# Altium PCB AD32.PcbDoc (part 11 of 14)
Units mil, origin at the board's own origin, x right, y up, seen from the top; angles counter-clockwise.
Board outline 7007.87 x 4368.85 mil, 12 copper layers (Top Layer, Int1 (GND), Int2 (AVDD), Int3 (DVDD), Int4 (GND), Int5 (ST), Int6 (SB), Int8 (AGND), Int7 (AVCC), Int9 (VCCA), Int10 (GND), Bottom Layer), stack 60.136 mil thick; 1350 components, 880 nets, 4712 pads, 2835 vias.
Unrouted connection lines stored in the file: 19.
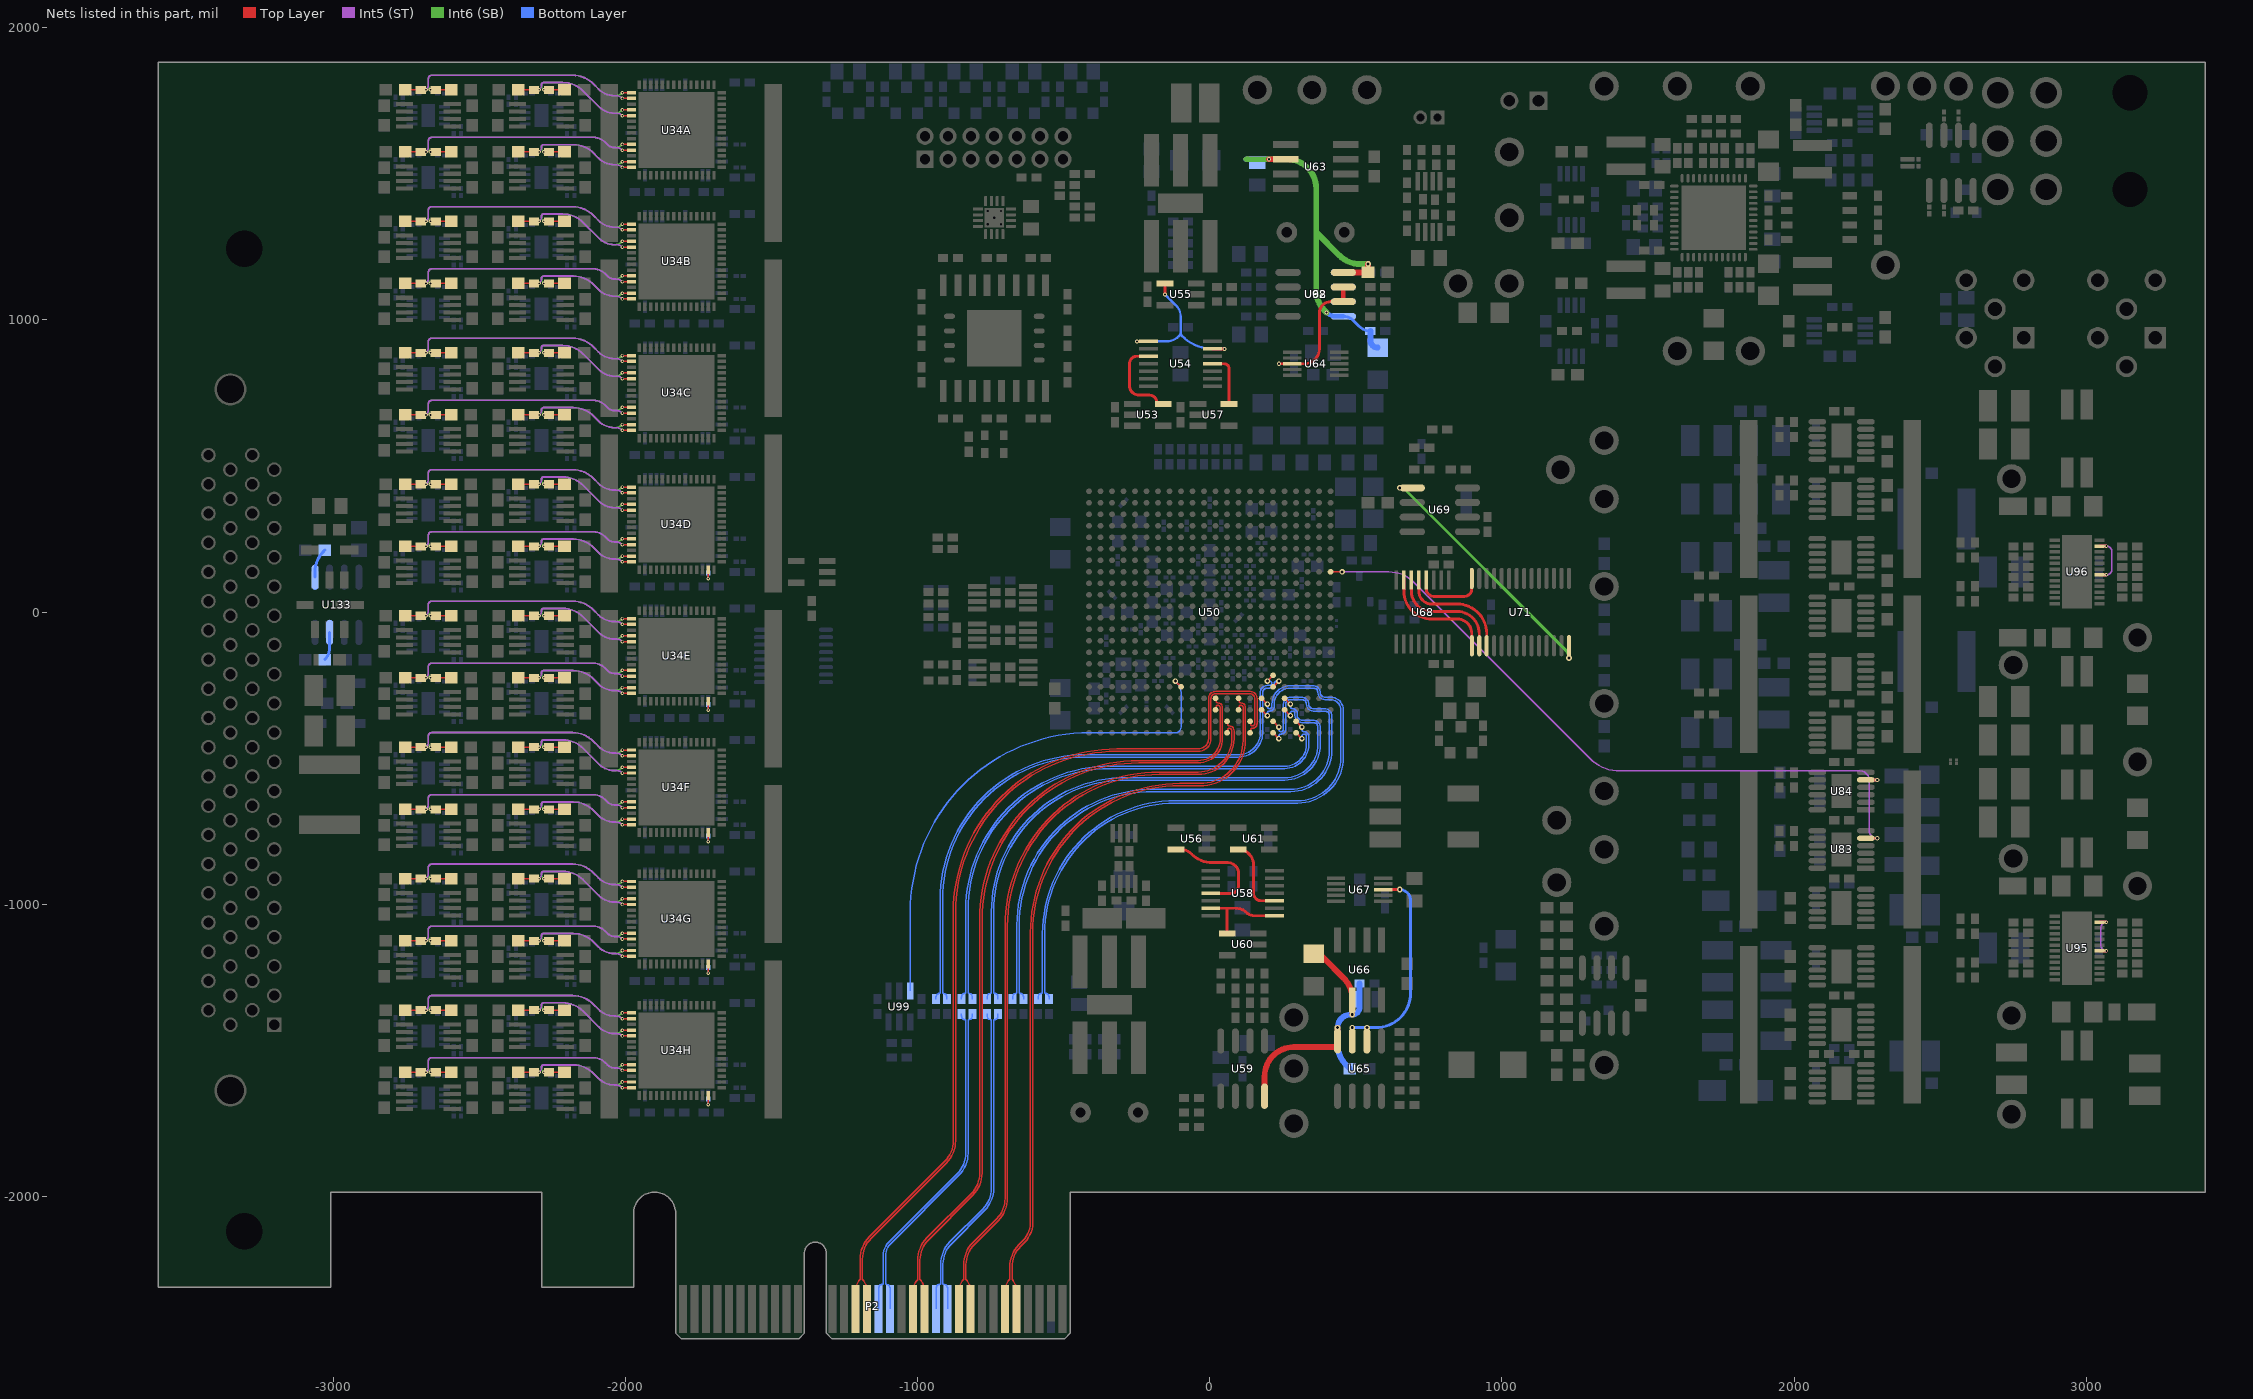
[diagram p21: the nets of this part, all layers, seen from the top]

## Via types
v1: diameter 12, hole 6, Top Layer to Bottom Layer, tented both sides, 1497 vias
v2: diameter 20, hole 10, Top Layer to Bottom Layer, tented both sides, 364 vias
v3: diameter 19, hole 10, Top Layer to Bottom Layer, tented both sides, 347 vias
v4: diameter 14, hole 7, Top Layer to Bottom Layer, tented both sides, 228 vias
v5: diameter 19.68, hole 7.87, Top Layer to Bottom Layer, 225 vias
v6: diameter 19.02, hole 10, Top Layer to Bottom Layer, tented both sides, 85 vias
v7: diameter 20, hole 10, Top Layer to Bottom Layer, 32 vias
v8: diameter 40, hole 20, Top Layer to Bottom Layer, tented both sides, 14 vias
v9: diameter 30, hole 15, Top Layer to Bottom Layer, tented both sides, 12 vias
v10: diameter 25, hole 13, Top Layer to Bottom Layer, 8 vias
v11: diameter 40, hole 20, Top Layer to Bottom Layer, 6 vias
v12: diameter 50, hole 20, Top Layer to Bottom Layer, 6 vias
v13: diameter 66, hole 47, Top Layer to Bottom Layer, tented both sides, 3 vias
v14: diameter 63, hole 45, Top Layer to Bottom Layer, 2 vias
v15: diameter 50, hole 25, Top Layer to Bottom Layer, 2 vias
v16: diameter 12, hole 6, Top Layer to Bottom Layer, 2 vias
v17: diameter 60, hole 40, Top Layer to Bottom Layer, tented both sides, 1 vias
v18: diameter 60, hole 40, Top Layer to Bottom Layer, 1 vias

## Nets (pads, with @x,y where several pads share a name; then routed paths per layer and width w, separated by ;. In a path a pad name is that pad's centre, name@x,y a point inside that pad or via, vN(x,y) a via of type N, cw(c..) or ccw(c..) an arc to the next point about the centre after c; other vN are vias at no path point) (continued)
NetR457D_1: R457D.1 U34D.55 | length 49.7
  Top Layer w5: v1(-1716.73,114.57) U34D.55@-1716.73,145.38
  Bottom Layer w5: v1(-1716.73,114.57) R457D.1@-1716.73,133.44
NetR457E_1: R457E.1 U34E.55 | length 49.7
  Top Layer w5: v1(-1716.73,-335.43) U34E.55@-1716.73,-304.62
  Bottom Layer w5: v1(-1716.73,-335.43) R457E.1@-1716.73,-316.56
NetR457F_1: R457F.1 U34F.55 | length 49.7
  Top Layer w5: v1(-1716.73,-785.43) U34F.55@-1716.73,-754.62
  Bottom Layer w5: v1(-1716.73,-785.43) R457F.1@-1716.73,-766.56
NetR457G_1: R457G.1 U34G.55 | length 49.7
  Top Layer w5: v1(-1716.73,-1235.43) U34G.55@-1716.73,-1204.62
  Bottom Layer w5: v1(-1716.73,-1235.43) R457G.1@-1716.73,-1216.56
NetR457H_1: R457H.1 U34H.55 | length 49.7
  Top Layer w5: v1(-1716.73,-1685.43) U34H.55@-1716.73,-1654.62
  Bottom Layer w5: v1(-1716.73,-1685.43) R457H.1@-1716.73,-1666.56
NetR665_1: R665.1 U133.3 | length 97.4
  Bottom Layer w10: R665.1@-3029.04,-162.5 ccw(c-3068.96,-122.58) -3012.5,-122.58 U133.3@-3012.5,-69.49
NetR666_1: R666.1 U133.5 | length 102.6
  Bottom Layer w10: U133.5@-3062.5,119.49 -3062.5,137.61 cw(c-2962.5,137.61) -3033.21,208.32 R666.1@-3029.04,212.5
NetU53_5: U53.5 U54.3 | length 332.7
  Top Layer w10: U54.3@-209.25,875.59 -250,875.59 ccw(c-250,850.59) -275,850.59 -275,775 ccw(c-242.5,775) -242.5,742.5 -205.89,742.5 cw(c-205.89,718.31) U53.5@-181.69,718.31 ; U53.5@-181.69,718.31 ccw(c-175.79,718.31) -175.79,712.4 U53.5@-159.35,712.4 ccw(c-165.26,712.4) -165.26,718.31 U53.5@-181.69,718.31
NetU54_1: U54.1 U54.13 U55.4 | length 602.1
  Top Layer w10: v4(-249.61,926.77) U54.1@-209.25,926.77 ; v4(-153.15,1087.5) U55.4@-153.15,1124.9 ; U54.13@9.25,901.18 v4(50,901.18)
  Bottom Layer w8: v4(-249.61,926.77) -148.58,926.77 ccw(c-148.58,987.97) -105.3,944.7 ccw(c-118.11,957.5) -100,957.5 ; v4(-153.15,1087.5) -115.45,1049.8 cw(c-152.75,1012.5) -100,1012.5 -100,957.5 ; v4(50,901.18) 10.36,901.18 cw(c10.36,1049.75) -94.7,944.7 cw(c-81.89,957.5) -100,957.5
NetU54_11: U54.11 U57.5 | length 187.3
  Top Layer w10: U54.11@9.25,850 50,850 cw(c50,834.35) 65.65,834.35 U57.5@65.65,712.4
NetU56_5: U56.5 U58.11 | length 399.6
  Top Layer w10: U56.5@-115.65,-812.4 -99.71,-812.4 cw(c-99.71,-865.03) -62.5,-827.81 -62.1,-828.21 ccw(c8.61,-757.5) 8.61,-857.5 61.61,-857.5 cw(c61.61,-894.31) 98.43,-894.31 98.43,-937.01 cw(c72.93,-937.01) 72.93,-962.5 U58.11@3.25,-962.5
NetU58_1: U58.1 U58.13 U60.4 | length 312.4
  Top Layer w10: U58.13@3.25,-1013.68 61.56,-1013.68 ; U60.4@59.35,-1100.1 59.35,-1019 cw(c66.88,-1019) 61.56,-1013.68 ; U58.1@221.75,-1039.27 152.38,-1039.27 cw(c152.38,-1000.97) 125.3,-1028.05 ccw(c90.6,-1062.75) 90.6,-1013.68 61.56,-1013.68
NetU58_3: U58.3 U61.5 | length 266.8
  Top Layer w10: U61.5@96.85,-812.4 cw(c96.85,-865.55) 150,-865.55 150,-962.5 ccw(c175.59,-962.5) 175.59,-988.09 U58.3@221.75,-988.09
NetU62_6: U62.6 U62.7 U64.3 | length 444.1
  Top Layer w10: v4(237.5,850) U64.3@281.79,850 325,850 ccw(c325,900) 375,900 375,1024.31 cw(c413.19,1024.31) 413.19,1062.5 U62.6@456.99,1062.5
  Top Layer w15: U62.6@456.99,1062.5 U62.7@456.99,1112.5
NetU65_6: U65.6 U65.7 U67.3 | length 790.4
  Top Layer w10: U65.7@487.5,-1468.01 v2(487.5,-1422.5) ; U65.6@537.5,-1468.01 v2(537.5,-1422.5) ; U67.3@593.21,-950 v2(650,-950)
  Bottom Layer w10: v2(487.5,-1422.5) v2(537.5,-1422.5) 567.87,-1422.5 ccw(c567.87,-1302.87) 687.5,-1302.87 687.5,-987.5 ccw(c650,-987.5) v2(650,-950)
NetU68_4: U68.4 U71.14 | length 250.3
  Top Layer w10: U68.4@741.14,109.25 741.14,79.16 ccw(c766.26,79.16) 766.26,54.04 871.63,54.04 ccw(c871.63,79.06) 896.65,79.06 U71.14@896.65,115.16
NetU68_5: U68.5 U71.17 | length 394.2
  Top Layer w10: U68.5@715.55,109.25 715.55,71.77 ccw(c759.76,71.77) 759.76,27.56 846.54,27.56 cw(c846.54,-73.74) 947.83,-73.74 U71.17@947.83,-115.16
NetU68_6: U68.6 U71.16 | length 394.2
  Top Layer w10: U68.6@689.96,109.25 689.96,71.77 ccw(c759.76,71.77) 759.76,1.97 846.54,1.97 cw(c846.54,-73.74) 922.24,-73.74 U71.16@922.24,-115.16
NetU68_7: U68.7 U71.15 | length 394.2
  Top Layer w10: U68.7@664.37,109.25 664.37,71.77 ccw(c759.76,71.77) 759.76,-23.62 846.54,-23.62 cw(c846.54,-73.74) 896.65,-73.74 U71.15@896.65,-115.16
NetU69_5: U69.5 U71.28 | length 869.2
  Top Layer w10: v2(1229.33,-157.48) U71.28@1229.33,-115.16
  Int6 (SB) w10: v3(650,425) cw(c650,394.82) 671.34,416.16 1218.26,-130.76 cw(c1191.55,-157.48) v2(1229.33,-157.48)
NetU95_18: U95.18 U95.23 | length 166.8
  Top Layer w10: U95.18@3045.25,-1159.84 v1(3068.75,-1159.84) ; U95.23@3045.25,-1061.42 v1(3068.75,-1061.42)
  Int5 (ST) w5: v1(3068.75,-1159.84) cw(c3068.75,-1141.09) 3050,-1141.09 3050,-1080.17 cw(c3068.75,-1080.17) v1(3068.75,-1061.42)
NetU96_18: U96.18 U96.23 | length 166.8
  Top Layer w10: U96.18@3045.25,127.66 v1(3068.75,127.66) ; U96.23@3045.25,226.08 v1(3068.75,226.08)
  Int5 (ST) w5: v1(3068.75,127.66) ccw(c3068.75,146.41) 3087.5,146.41 3087.5,207.33 ccw(c3068.75,207.33) v1(3068.75,226.08)
OUT1A_N: C3A.1 R20A.2 U34A.30 | length 837.4
  Top Layer w5: R20A.2@-2754.04,1787.5 C3A.1@-2700.59,1787.5 v1(-2682.5,1787.5) ; v1(-2010.43,1758.27) U34A.30@-1979.62,1758.27
  Int5 (ST) w6: v1(-2682.5,1787.5) -2682.07,1787.93 ccw(c-2699.14,1805) -2675,1805 -2675,1825 cw(c-2662.5,1825) -2662.5,1837.5 -2181.09,1837.5 cw(c-2181.09,1737.5) -2110.38,1808.21 -2092.41,1790.24 ccw(c-2037.5,1845.15) -2037.5,1767.5 -2032.72,1767.5 cw(c-2032.72,1735.98) v1(-2010.43,1758.27)
OUT1A_P: C3A.2 R36A.2 U34A.29 | length 837.8
  Top Layer w5: v1(-2667.5,1787.5) C3A.2@-2649.41,1787.5 R36A.2@-2595.96,1787.5 ; v1(-2010.43,1777.95) U34A.29@-1979.62,1777.95
  Int6 (SB) w6: v1(-2667.5,1787.5) -2667.93,1787.93 cw(c-2650.86,1805) -2675,1805 -2675,1825 cw(c-2662.5,1825) -2662.5,1837.5 -2181.09,1837.5 cw(c-2181.09,1737.5) -2110.38,1808.21 -2092.41,1790.24 ccw(c-2037.5,1845.15) -2037.5,1767.5 -2035.67,1767.5 ccw(c-2035.67,1803.19) v1(-2010.43,1777.95)
OUT1B_N: C3B.1 R20B.2 U34B.30 | length 837.4
  Top Layer w5: R20B.2@-2754.04,1337.5 C3B.1@-2700.59,1337.5 v1(-2682.5,1337.5) ; v1(-2010.43,1308.27) U34B.30@-1979.62,1308.27
  Int5 (ST) w6: v1(-2682.5,1337.5) -2682.07,1337.93 ccw(c-2699.14,1355) -2675,1355 -2675,1375 cw(c-2662.5,1375) -2662.5,1387.5 -2181.09,1387.5 cw(c-2181.09,1287.5) -2110.38,1358.21 -2092.41,1340.24 ccw(c-2037.5,1395.15) -2037.5,1317.5 -2032.72,1317.5 cw(c-2032.72,1285.98) v1(-2010.43,1308.27)
OUT1B_P: C3B.2 R36B.2 U34B.29 | length 837.8
  Top Layer w5: v1(-2667.5,1337.5) C3B.2@-2649.41,1337.5 R36B.2@-2595.96,1337.5 ; v1(-2010.43,1327.95) U34B.29@-1979.62,1327.95
  Int6 (SB) w6: v1(-2667.5,1337.5) -2667.93,1337.93 cw(c-2650.86,1355) -2675,1355 -2675,1375 cw(c-2662.5,1375) -2662.5,1387.5 -2181.09,1387.5 cw(c-2181.09,1287.5) -2110.38,1358.21 -2092.41,1340.24 ccw(c-2037.5,1395.15) -2037.5,1317.5 -2035.67,1317.5 ccw(c-2035.67,1353.19) v1(-2010.43,1327.95)
OUT1C_N: C3C.1 R20C.2 U34C.30 | length 837.4
  Top Layer w5: R20C.2@-2754.04,887.5 C3C.1@-2700.59,887.5 v1(-2682.5,887.5) ; v1(-2010.43,858.27) U34C.30@-1979.62,858.27
  Int5 (ST) w6: v1(-2682.5,887.5) -2682.07,887.93 ccw(c-2699.14,905) -2675,905 -2675,925 cw(c-2662.5,925) -2662.5,937.5 -2181.09,937.5 cw(c-2181.09,837.5) -2110.38,908.21 -2092.41,890.24 ccw(c-2037.5,945.15) -2037.5,867.5 -2032.72,867.5 cw(c-2032.72,835.98) v1(-2010.43,858.27)
OUT1C_P: C3C.2 R36C.2 U34C.29 | length 837.8
  Top Layer w5: v1(-2667.5,887.5) C3C.2@-2649.41,887.5 R36C.2@-2595.96,887.5 ; v1(-2010.43,877.95) U34C.29@-1979.62,877.95
  Int6 (SB) w6: v1(-2667.5,887.5) -2667.93,887.93 cw(c-2650.86,905) -2675,905 -2675,925 cw(c-2662.5,925) -2662.5,937.5 -2181.09,937.5 cw(c-2181.09,837.5) -2110.38,908.21 -2092.41,890.24 ccw(c-2037.5,945.15) -2037.5,867.5 -2035.67,867.5 ccw(c-2035.67,903.19) v1(-2010.43,877.95)
OUT1D_N: C3D.1 R20D.2 U34D.30 | length 837.4
  Top Layer w5: R20D.2@-2754.04,437.5 C3D.1@-2700.59,437.5 v1(-2682.5,437.5) ; v1(-2010.43,408.27) U34D.30@-1979.62,408.27
  Int5 (ST) w6: v1(-2682.5,437.5) -2682.07,437.93 ccw(c-2699.14,455) -2675,455 -2675,475 cw(c-2662.5,475) -2662.5,487.5 -2181.09,487.5 cw(c-2181.09,387.5) -2110.38,458.21 -2092.41,440.24 ccw(c-2037.5,495.15) -2037.5,417.5 -2032.72,417.5 cw(c-2032.72,385.98) v1(-2010.43,408.27)
OUT1D_P: C3D.2 R36D.2 U34D.29 | length 837.8
  Top Layer w5: v1(-2667.5,437.5) C3D.2@-2649.41,437.5 R36D.2@-2595.96,437.5 ; v1(-2010.43,427.95) U34D.29@-1979.62,427.95
  Int6 (SB) w6: v1(-2667.5,437.5) -2667.93,437.93 cw(c-2650.86,455) -2675,455 -2675,475 cw(c-2662.5,475) -2662.5,487.5 -2181.09,487.5 cw(c-2181.09,387.5) -2110.38,458.21 -2092.41,440.24 ccw(c-2037.5,495.15) -2037.5,417.5 -2035.67,417.5 ccw(c-2035.67,453.19) v1(-2010.43,427.95)
OUT1E_N: C3E.1 R20E.2 U34E.30 | length 837.4
  Top Layer w5: R20E.2@-2754.04,-12.5 C3E.1@-2700.59,-12.5 v1(-2682.5,-12.5) ; v1(-2010.43,-41.73) U34E.30@-1979.62,-41.73
  Int5 (ST) w6: v1(-2682.5,-12.5) -2682.07,-12.07 ccw(c-2699.14,5) -2675,5 -2675,25 cw(c-2662.5,25) -2662.5,37.5 -2181.09,37.5 cw(c-2181.09,-62.5) -2110.38,8.21 -2092.41,-9.76 ccw(c-2037.5,45.15) -2037.5,-32.5 -2032.72,-32.5 cw(c-2032.72,-64.02) v1(-2010.43,-41.73)
OUT1E_P: C3E.2 R36E.2 U34E.29 | length 837.8
  Top Layer w5: v1(-2667.5,-12.5) C3E.2@-2649.41,-12.5 R36E.2@-2595.96,-12.5 ; v1(-2010.43,-22.05) U34E.29@-1979.62,-22.05
  Int6 (SB) w6: v1(-2667.5,-12.5) -2667.93,-12.07 cw(c-2650.86,5) -2675,5 -2675,25 cw(c-2662.5,25) -2662.5,37.5 -2181.09,37.5 cw(c-2181.09,-62.5) -2110.38,8.21 -2092.41,-9.76 ccw(c-2037.5,45.15) -2037.5,-32.5 -2035.67,-32.5 ccw(c-2035.67,3.19) v1(-2010.43,-22.05)
OUT1F_N: C3F.1 R20F.2 U34F.30 | length 837.4
  Top Layer w5: R20F.2@-2754.04,-462.5 C3F.1@-2700.59,-462.5 v1(-2682.5,-462.5) ; v1(-2010.43,-491.73) U34F.30@-1979.62,-491.73
  Int5 (ST) w6: v1(-2682.5,-462.5) -2682.07,-462.07 ccw(c-2699.14,-445) -2675,-445 -2675,-425 cw(c-2662.5,-425) -2662.5,-412.5 -2181.09,-412.5 cw(c-2181.09,-512.5) -2110.38,-441.79 -2092.41,-459.76 ccw(c-2037.5,-404.85) -2037.5,-482.5 -2032.72,-482.5 cw(c-2032.72,-514.02) v1(-2010.43,-491.73)
OUT1F_P: C3F.2 R36F.2 U34F.29 | length 837.8
  Top Layer w5: v1(-2667.5,-462.5) C3F.2@-2649.41,-462.5 R36F.2@-2595.96,-462.5 ; v1(-2010.43,-472.05) U34F.29@-1979.62,-472.05
  Int6 (SB) w6: v1(-2667.5,-462.5) -2667.93,-462.07 cw(c-2650.86,-445) -2675,-445 -2675,-425 cw(c-2662.5,-425) -2662.5,-412.5 -2181.09,-412.5 cw(c-2181.09,-512.5) -2110.38,-441.79 -2092.41,-459.76 ccw(c-2037.5,-404.85) -2037.5,-482.5 -2035.67,-482.5 ccw(c-2035.67,-446.81) v1(-2010.43,-472.05)
OUT1G_N: C3G.1 R20G.2 U34G.30 | length 837.4
  Top Layer w5: R20G.2@-2754.04,-912.5 C3G.1@-2700.59,-912.5 v1(-2682.5,-912.5) ; v1(-2010.43,-941.73) U34G.30@-1979.62,-941.73
  Int5 (ST) w6: v1(-2682.5,-912.5) -2682.07,-912.07 ccw(c-2699.14,-895) -2675,-895 -2675,-875 cw(c-2662.5,-875) -2662.5,-862.5 -2181.09,-862.5 cw(c-2181.09,-962.5) -2110.38,-891.79 -2092.41,-909.76 ccw(c-2037.5,-854.85) -2037.5,-932.5 -2032.72,-932.5 cw(c-2032.72,-964.02) v1(-2010.43,-941.73)
OUT1G_P: C3G.2 R36G.2 U34G.29 | length 837.8
  Top Layer w5: v1(-2667.5,-912.5) C3G.2@-2649.41,-912.5 R36G.2@-2595.96,-912.5 ; v1(-2010.43,-922.05) U34G.29@-1979.62,-922.05
  Int6 (SB) w6: v1(-2667.5,-912.5) -2667.93,-912.07 cw(c-2650.86,-895) -2675,-895 -2675,-875 cw(c-2662.5,-875) -2662.5,-862.5 -2181.09,-862.5 cw(c-2181.09,-962.5) -2110.38,-891.79 -2092.41,-909.76 ccw(c-2037.5,-854.85) -2037.5,-932.5 -2035.67,-932.5 ccw(c-2035.67,-896.81) v1(-2010.43,-922.05)
OUT1H_N: C3H.1 R20H.2 U34H.30 | length 837.4
  Top Layer w5: R20H.2@-2754.04,-1362.5 C3H.1@-2700.59,-1362.5 v1(-2682.5,-1362.5) ; v1(-2010.43,-1391.73) U34H.30@-1979.62,-1391.73
  Int5 (ST) w6: v1(-2682.5,-1362.5) -2682.07,-1362.07 ccw(c-2699.14,-1345) -2675,-1345 -2675,-1325 cw(c-2662.5,-1325) -2662.5,-1312.5 -2181.09,-1312.5 cw(c-2181.09,-1412.5) -2110.38,-1341.79 -2092.41,-1359.76 ccw(c-2037.5,-1304.85) -2037.5,-1382.5 -2032.72,-1382.5 cw(c-2032.72,-1414.02) v1(-2010.43,-1391.73)
OUT1H_P: C3H.2 R36H.2 U34H.29 | length 837.8
  Top Layer w5: v1(-2667.5,-1362.5) C3H.2@-2649.41,-1362.5 R36H.2@-2595.96,-1362.5 ; v1(-2010.43,-1372.05) U34H.29@-1979.62,-1372.05
  Int6 (SB) w6: v1(-2667.5,-1362.5) -2667.93,-1362.07 cw(c-2650.86,-1345) -2675,-1345 -2675,-1325 cw(c-2662.5,-1325) -2662.5,-1312.5 -2181.09,-1312.5 cw(c-2181.09,-1412.5) -2110.38,-1341.79 -2092.41,-1359.76 ccw(c-2037.5,-1304.85) -2037.5,-1382.5 -2035.67,-1382.5 ccw(c-2035.67,-1346.81) v1(-2010.43,-1372.05)
OUT2A_N: C19A.1 R84A.2 U34A.33 | length 441.4
  Top Layer w5: R84A.2@-2366.54,1787.5 C19A.1@-2313.09,1787.5 v1(-2295,1787.5) ; v1(-2010.43,1699.21) U34A.33@-1979.62,1699.21
  Int5 (ST) w6: v1(-2295,1787.5) -2294.57,1787.93 ccw(c-2311.64,1805) -2287.5,1805 cw(c-2280,1805) -2280,1812.5 -2215.14,1812.5 cw(c-2215.14,1712.5) -2144.43,1783.21 -2090.8,1729.58 ccw(c-2037.5,1782.87) -2037.5,1707.5 -2030.44,1707.5 cw(c-2030.44,1679.2) v1(-2010.43,1699.21)
OUT2A_P: C19A.2 R100A.2 U34A.32 | length 442.3
  Top Layer w5: v1(-2280,1787.5) C19A.2@-2261.91,1787.5 R100A.2@-2208.46,1787.5 ; v1(-2010.43,1718.9) U34A.32@-1979.62,1718.9
  Int6 (SB) w6: v1(-2280,1787.5) -2280.43,1787.93 cw(c-2263.36,1805) -2287.5,1805 cw(c-2280,1805) -2280,1812.5 -2215.14,1812.5 cw(c-2215.14,1712.5) -2144.43,1783.21 -2090.8,1729.58 ccw(c-2037.5,1782.87) -2037.5,1707.5 ccw(c-2037.5,1745.33) -2010.75,1718.58 v1(-2010.43,1718.9)
OUT2B_N: C19B.1 R84B.2 U34B.33 | length 441.4
  Top Layer w5: R84B.2@-2366.54,1337.5 C19B.1@-2313.09,1337.5 v1(-2295,1337.5) ; v1(-2010.43,1249.21) U34B.33@-1979.62,1249.21
  Int5 (ST) w6: v1(-2295,1337.5) -2294.57,1337.93 ccw(c-2311.64,1355) -2287.5,1355 cw(c-2280,1355) -2280,1362.5 -2215.14,1362.5 cw(c-2215.14,1262.5) -2144.43,1333.21 -2090.8,1279.58 ccw(c-2037.5,1332.87) -2037.5,1257.5 -2030.44,1257.5 cw(c-2030.44,1229.2) v1(-2010.43,1249.21)
OUT2B_P: C19B.2 R100B.2 U34B.32 | length 442.3
  Top Layer w5: v1(-2280,1337.5) C19B.2@-2261.91,1337.5 R100B.2@-2208.46,1337.5 ; v1(-2010.43,1268.9) U34B.32@-1979.62,1268.9
  Int6 (SB) w6: v1(-2280,1337.5) -2280.43,1337.93 cw(c-2263.36,1355) -2287.5,1355 cw(c-2280,1355) -2280,1362.5 -2215.14,1362.5 cw(c-2215.14,1262.5) -2144.43,1333.21 -2090.8,1279.58 ccw(c-2037.5,1332.87) -2037.5,1257.5 ccw(c-2037.5,1295.33) -2010.75,1268.58 v1(-2010.43,1268.9)
OUT2C_N: C19C.1 R84C.2 U34C.33 | length 441.4
  Top Layer w5: R84C.2@-2366.54,887.5 C19C.1@-2313.09,887.5 v1(-2295,887.5) ; v1(-2010.43,799.21) U34C.33@-1979.62,799.21
  Int5 (ST) w6: v1(-2295,887.5) -2294.57,887.93 ccw(c-2311.64,905) -2287.5,905 cw(c-2280,905) -2280,912.5 -2215.14,912.5 cw(c-2215.14,812.5) -2144.43,883.21 -2090.8,829.58 ccw(c-2037.5,882.87) -2037.5,807.5 -2030.44,807.5 cw(c-2030.44,779.2) v1(-2010.43,799.21)
OUT2C_P: C19C.2 R100C.2 U34C.32 | length 442.3
  Top Layer w5: v1(-2280,887.5) C19C.2@-2261.91,887.5 R100C.2@-2208.46,887.5 ; v1(-2010.43,818.9) U34C.32@-1979.62,818.9
  Int6 (SB) w6: v1(-2280,887.5) -2280.43,887.93 cw(c-2263.36,905) -2287.5,905 cw(c-2280,905) -2280,912.5 -2215.14,912.5 cw(c-2215.14,812.5) -2144.43,883.21 -2090.8,829.58 ccw(c-2037.5,882.87) -2037.5,807.5 ccw(c-2037.5,845.33) -2010.75,818.58 v1(-2010.43,818.9)
OUT2D_N: C19D.1 R84D.2 U34D.33 | length 441.4
  Top Layer w5: R84D.2@-2366.54,437.5 C19D.1@-2313.09,437.5 v1(-2295,437.5) ; v1(-2010.43,349.21) U34D.33@-1979.62,349.21
  Int5 (ST) w6: v1(-2295,437.5) -2294.57,437.93 ccw(c-2311.64,455) -2287.5,455 cw(c-2280,455) -2280,462.5 -2215.14,462.5 cw(c-2215.14,362.5) -2144.43,433.21 -2090.8,379.58 ccw(c-2037.5,432.87) -2037.5,357.5 -2030.44,357.5 cw(c-2030.44,329.2) v1(-2010.43,349.21)
OUT2D_P: C19D.2 R100D.2 U34D.32 | length 442.3
  Top Layer w5: v1(-2280,437.5) C19D.2@-2261.91,437.5 R100D.2@-2208.46,437.5 ; v1(-2010.43,368.9) U34D.32@-1979.62,368.9
  Int6 (SB) w6: v1(-2280,437.5) -2280.43,437.93 cw(c-2263.36,455) -2287.5,455 cw(c-2280,455) -2280,462.5 -2215.14,462.5 cw(c-2215.14,362.5) -2144.43,433.21 -2090.8,379.58 ccw(c-2037.5,432.87) -2037.5,357.5 ccw(c-2037.5,395.33) -2010.75,368.58 v1(-2010.43,368.9)
OUT2E_N: C19E.1 R84E.2 U34E.33 | length 441.4
  Top Layer w5: R84E.2@-2366.54,-12.5 C19E.1@-2313.09,-12.5 v1(-2295,-12.5) ; v1(-2010.43,-100.79) U34E.33@-1979.62,-100.79
  Int5 (ST) w6: v1(-2295,-12.5) -2294.57,-12.07 ccw(c-2311.64,5) -2287.5,5 cw(c-2280,5) -2280,12.5 -2215.14,12.5 cw(c-2215.14,-87.5) -2144.43,-16.79 -2090.8,-70.42 ccw(c-2037.5,-17.13) -2037.5,-92.5 -2030.44,-92.5 cw(c-2030.44,-120.8) v1(-2010.43,-100.79)
OUT2E_P: C19E.2 R100E.2 U34E.32 | length 442.3
  Top Layer w5: v1(-2280,-12.5) C19E.2@-2261.91,-12.5 R100E.2@-2208.46,-12.5 ; v1(-2010.43,-81.1) U34E.32@-1979.62,-81.1
  Int6 (SB) w6: v1(-2280,-12.5) -2280.43,-12.07 cw(c-2263.36,5) -2287.5,5 cw(c-2280,5) -2280,12.5 -2215.14,12.5 cw(c-2215.14,-87.5) -2144.43,-16.79 -2090.8,-70.42 ccw(c-2037.5,-17.13) -2037.5,-92.5 ccw(c-2037.5,-54.67) -2010.75,-81.42 v1(-2010.43,-81.1)
OUT2F_N: C19F.1 R84F.2 U34F.33 | length 441.4
  Top Layer w5: R84F.2@-2366.54,-462.5 C19F.1@-2313.09,-462.5 v1(-2295,-462.5) ; v1(-2010.43,-550.79) U34F.33@-1979.62,-550.79
  Int5 (ST) w6: v1(-2295,-462.5) -2294.57,-462.07 ccw(c-2311.64,-445) -2287.5,-445 cw(c-2280,-445) -2280,-437.5 -2215.14,-437.5 cw(c-2215.14,-537.5) -2144.43,-466.79 -2090.8,-520.42 ccw(c-2037.5,-467.13) -2037.5,-542.5 -2030.44,-542.5 cw(c-2030.44,-570.8) v1(-2010.43,-550.79)
OUT2F_P: C19F.2 R100F.2 U34F.32 | length 442.3
  Top Layer w5: v1(-2280,-462.5) C19F.2@-2261.91,-462.5 R100F.2@-2208.46,-462.5 ; v1(-2010.43,-531.1) U34F.32@-1979.62,-531.1
  Int6 (SB) w6: v1(-2280,-462.5) -2280.43,-462.07 cw(c-2263.36,-445) -2287.5,-445 cw(c-2280,-445) -2280,-437.5 -2215.14,-437.5 cw(c-2215.14,-537.5) -2144.43,-466.79 -2090.8,-520.42 ccw(c-2037.5,-467.13) -2037.5,-542.5 ccw(c-2037.5,-504.67) -2010.75,-531.42 v1(-2010.43,-531.1)
OUT2G_N: C19G.1 R84G.2 U34G.33 | length 441.4
  Top Layer w5: R84G.2@-2366.54,-912.5 C19G.1@-2313.09,-912.5 v1(-2295,-912.5) ; v1(-2010.43,-1000.79) U34G.33@-1979.62,-1000.79
  Int5 (ST) w6: v1(-2295,-912.5) -2294.57,-912.07 ccw(c-2311.64,-895) -2287.5,-895 cw(c-2280,-895) -2280,-887.5 -2215.14,-887.5 cw(c-2215.14,-987.5) -2144.43,-916.79 -2090.8,-970.42 ccw(c-2037.5,-917.13) -2037.5,-992.5 -2030.44,-992.5 cw(c-2030.44,-1020.8) v1(-2010.43,-1000.79)
OUT2G_P: C19G.2 R100G.2 U34G.32 | length 442.3
  Top Layer w5: v1(-2280,-912.5) C19G.2@-2261.91,-912.5 R100G.2@-2208.46,-912.5 ; v1(-2010.43,-981.1) U34G.32@-1979.62,-981.1
  Int6 (SB) w6: v1(-2280,-912.5) -2280.43,-912.07 cw(c-2263.36,-895) -2287.5,-895 cw(c-2280,-895) -2280,-887.5 -2215.14,-887.5 cw(c-2215.14,-987.5) -2144.43,-916.79 -2090.8,-970.42 ccw(c-2037.5,-917.13) -2037.5,-992.5 ccw(c-2037.5,-954.67) -2010.75,-981.42 v1(-2010.43,-981.1)
OUT2H_N: C19H.1 R84H.2 U34H.33 | length 441.4
  Top Layer w5: R84H.2@-2366.54,-1362.5 C19H.1@-2313.09,-1362.5 v1(-2295,-1362.5) ; v1(-2010.43,-1450.79) U34H.33@-1979.62,-1450.79
  Int5 (ST) w6: v1(-2295,-1362.5) -2294.57,-1362.07 ccw(c-2311.64,-1345) -2287.5,-1345 cw(c-2280,-1345) -2280,-1337.5 -2215.14,-1337.5 cw(c-2215.14,-1437.5) -2144.43,-1366.79 -2090.8,-1420.42 ccw(c-2037.5,-1367.13) -2037.5,-1442.5 -2030.44,-1442.5 cw(c-2030.44,-1470.8) v1(-2010.43,-1450.79)
OUT2H_P: C19H.2 R100H.2 U34H.32 | length 442.3
  Top Layer w5: v1(-2280,-1362.5) C19H.2@-2261.91,-1362.5 R100H.2@-2208.46,-1362.5 ; v1(-2010.43,-1431.1) U34H.32@-1979.62,-1431.1
  Int6 (SB) w6: v1(-2280,-1362.5) -2280.43,-1362.07 cw(c-2263.36,-1345) -2287.5,-1345 cw(c-2280,-1345) -2280,-1337.5 -2215.14,-1337.5 cw(c-2215.14,-1437.5) -2144.43,-1366.79 -2090.8,-1420.42 ccw(c-2037.5,-1367.13) -2037.5,-1442.5 ccw(c-2037.5,-1404.67) -2010.75,-1431.42 v1(-2010.43,-1431.1)
OUT3A_N: C11A.1 R28A.2 U34A.39 | length 826.7
  Top Layer w5: R28A.2@-2754.04,1575 C11A.1@-2700.59,1575 v1(-2682.5,1575) ; v1(-2010.43,1581.1) U34A.39@-1979.62,1581.1
  Int5 (ST) w6: v1(-2682.5,1575) -2682.07,1575.43 ccw(c-2699.14,1592.5) -2675,1592.5 -2675,1612.5 cw(c-2662.5,1612.5) -2662.5,1625 -2110.52,1625 cw(c-2110.52,1566.71) -2069.3,1607.93 -2061.19,1599.81 ccw(c-2037.5,1623.5) -2037.5,1590 -2031.91,1590 cw(c-2031.91,1559.62) v1@-2010.56,1581.23 ; v1@-2010.56,1581.23 cw(c-2031.91,1559.62) v1(-2010.43,1581.1) v1@-2010.56,1581.23
OUT3A_P: C11A.2 R44A.2 U34A.38 | length 827
  Top Layer w5: v1(-2667.5,1575) C11A.2@-2649.41,1575 R44A.2@-2595.96,1575 ; v1(-2010.43,1600.79) U34A.38@-1979.62,1600.79
  Int6 (SB) w6: v1(-2667.5,1575) -2667.93,1575.43 cw(c-2650.86,1592.5) -2675,1592.5 -2675,1612.5 cw(c-2662.5,1612.5) -2662.5,1625 -2110.52,1625 cw(c-2110.52,1566.71) -2069.3,1607.93 -2061.19,1599.81 ccw(c-2037.5,1623.5) -2037.5,1590 -2036.47,1590 ccw(c-2036.47,1626.83) v1(-2010.43,1600.79)
OUT3B_N: C11B.1 R28B.2 U34B.39 | length 826.7
  Top Layer w5: R28B.2@-2754.04,1125 C11B.1@-2700.59,1125 v1(-2682.5,1125) ; v1(-2010.43,1131.1) U34B.39@-1979.62,1131.1
  Int5 (ST) w6: v1(-2682.5,1125) -2682.07,1125.43 ccw(c-2699.14,1142.5) -2675,1142.5 -2675,1162.5 cw(c-2662.5,1162.5) -2662.5,1175 -2110.52,1175 cw(c-2110.52,1116.71) -2069.3,1157.93 -2061.19,1149.81 ccw(c-2037.5,1173.5) -2037.5,1140 -2031.91,1140 cw(c-2031.91,1109.62) v1@-2010.56,1131.23 ; v1@-2010.56,1131.23 cw(c-2031.91,1109.62) v1(-2010.43,1131.1) v1@-2010.56,1131.23
OUT3B_P: C11B.2 R44B.2 U34B.38 | length 827
  Top Layer w5: v1(-2667.5,1125) C11B.2@-2649.41,1125 R44B.2@-2595.96,1125 ; v1(-2010.43,1150.79) U34B.38@-1979.62,1150.79
  Int6 (SB) w6: v1(-2667.5,1125) -2667.93,1125.43 cw(c-2650.86,1142.5) -2675,1142.5 -2675,1162.5 cw(c-2662.5,1162.5) -2662.5,1175 -2110.52,1175 cw(c-2110.52,1116.71) -2069.3,1157.93 -2061.19,1149.81 ccw(c-2037.5,1173.5) -2037.5,1140 -2036.47,1140 ccw(c-2036.47,1176.83) v1(-2010.43,1150.79)
OUT3C_N: C11C.1 R28C.2 U34C.39 | length 826.7
  Top Layer w5: R28C.2@-2754.04,675 C11C.1@-2700.59,675 v1(-2682.5,675) ; v1(-2010.43,681.1) U34C.39@-1979.62,681.1
  Int5 (ST) w6: v1(-2682.5,675) -2682.07,675.43 ccw(c-2699.14,692.5) -2675,692.5 -2675,712.5 cw(c-2662.5,712.5) -2662.5,725 -2110.52,725 cw(c-2110.52,666.71) -2069.3,707.93 -2061.19,699.81 ccw(c-2037.5,723.5) -2037.5,690 -2031.91,690 cw(c-2031.91,659.62) v1@-2010.56,681.23 ; v1@-2010.56,681.23 cw(c-2031.91,659.62) v1(-2010.43,681.1) v1@-2010.56,681.23
OUT3C_P: C11C.2 R44C.2 U34C.38 | length 827
  Top Layer w5: v1(-2667.5,675) C11C.2@-2649.41,675 R44C.2@-2595.96,675 ; v1(-2010.43,700.79) U34C.38@-1979.62,700.79
  Int6 (SB) w6: v1(-2667.5,675) -2667.93,675.43 cw(c-2650.86,692.5) -2675,692.5 -2675,712.5 cw(c-2662.5,712.5) -2662.5,725 -2110.52,725 cw(c-2110.52,666.71) -2069.3,707.93 -2061.19,699.81 ccw(c-2037.5,723.5) -2037.5,690 -2036.47,690 ccw(c-2036.47,726.83) v1(-2010.43,700.79)
OUT3D_N: C11D.1 R28D.2 U34D.39 | length 826.7
  Top Layer w5: R28D.2@-2754.04,225 C11D.1@-2700.59,225 v1(-2682.5,225) ; v1(-2010.43,231.1) U34D.39@-1979.62,231.1
  Int5 (ST) w6: v1(-2682.5,225) -2682.07,225.43 ccw(c-2699.14,242.5) -2675,242.5 -2675,262.5 cw(c-2662.5,262.5) -2662.5,275 -2110.52,275 cw(c-2110.52,216.71) -2069.3,257.93 -2061.19,249.81 ccw(c-2037.5,273.5) -2037.5,240 -2031.91,240 cw(c-2031.91,209.62) v1@-2010.56,231.23 ; v1@-2010.56,231.23 cw(c-2031.91,209.62) v1(-2010.43,231.1) v1@-2010.56,231.23
OUT3D_P: C11D.2 R44D.2 U34D.38 | length 827
  Top Layer w5: v1(-2667.5,225) C11D.2@-2649.41,225 R44D.2@-2595.96,225 ; v1(-2010.43,250.79) U34D.38@-1979.62,250.79
  Int6 (SB) w6: v1(-2667.5,225) -2667.93,225.43 cw(c-2650.86,242.5) -2675,242.5 -2675,262.5 cw(c-2662.5,262.5) -2662.5,275 -2110.52,275 cw(c-2110.52,216.71) -2069.3,257.93 -2061.19,249.81 ccw(c-2037.5,273.5) -2037.5,240 -2036.47,240 ccw(c-2036.47,276.83) v1(-2010.43,250.79)
OUT3E_N: C11E.1 R28E.2 U34E.39 | length 826.7
  Top Layer w5: R28E.2@-2754.04,-225 C11E.1@-2700.59,-225 v1(-2682.5,-225) ; v1(-2010.43,-218.9) U34E.39@-1979.62,-218.9
  Int5 (ST) w6: v1(-2682.5,-225) -2682.07,-224.57 ccw(c-2699.14,-207.5) -2675,-207.5 -2675,-187.5 cw(c-2662.5,-187.5) -2662.5,-175 -2110.52,-175 cw(c-2110.52,-233.29) -2069.3,-192.07 -2061.19,-200.19 ccw(c-2037.5,-176.5) -2037.5,-210 -2031.91,-210 cw(c-2031.91,-240.38) v1@-2010.56,-218.77 ; v1@-2010.56,-218.77 cw(c-2031.91,-240.38) v1(-2010.43,-218.9) v1@-2010.56,-218.77
OUT3E_P: C11E.2 R44E.2 U34E.38 | length 827
  Top Layer w5: v1(-2667.5,-225) C11E.2@-2649.41,-225 R44E.2@-2595.96,-225 ; v1(-2010.43,-199.21) U34E.38@-1979.62,-199.21
  Int6 (SB) w6: v1(-2667.5,-225) -2667.93,-224.57 cw(c-2650.86,-207.5) -2675,-207.5 -2675,-187.5 cw(c-2662.5,-187.5) -2662.5,-175 -2110.52,-175 cw(c-2110.52,-233.29) -2069.3,-192.07 -2061.19,-200.19 ccw(c-2037.5,-176.5) -2037.5,-210 -2036.47,-210 ccw(c-2036.47,-173.17) v1(-2010.43,-199.21)
OUT3F_N: C11F.1 R28F.2 U34F.39 | length 826.7
  Top Layer w5: R28F.2@-2754.04,-675 C11F.1@-2700.59,-675 v1(-2682.5,-675) ; v1(-2010.43,-668.9) U34F.39@-1979.62,-668.9
  Int5 (ST) w6: v1(-2682.5,-675) -2682.07,-674.57 ccw(c-2699.14,-657.5) -2675,-657.5 -2675,-637.5 cw(c-2662.5,-637.5) -2662.5,-625 -2110.52,-625 cw(c-2110.52,-683.29) -2069.3,-642.07 -2061.19,-650.19 ccw(c-2037.5,-626.5) -2037.5,-660 -2031.91,-660 cw(c-2031.91,-690.38) v1@-2010.56,-668.77 ; v1@-2010.56,-668.77 cw(c-2031.91,-690.38) v1(-2010.43,-668.9) v1@-2010.56,-668.77
OUT3F_P: C11F.2 R44F.2 U34F.38 | length 827
  Top Layer w5: v1(-2667.5,-675) C11F.2@-2649.41,-675 R44F.2@-2595.96,-675 ; v1(-2010.43,-649.21) U34F.38@-1979.62,-649.21
  Int6 (SB) w6: v1(-2667.5,-675) -2667.93,-674.57 cw(c-2650.86,-657.5) -2675,-657.5 -2675,-637.5 cw(c-2662.5,-637.5) -2662.5,-625 -2110.52,-625 cw(c-2110.52,-683.29) -2069.3,-642.07 -2061.19,-650.19 ccw(c-2037.5,-626.5) -2037.5,-660 -2036.47,-660 ccw(c-2036.47,-623.17) v1(-2010.43,-649.21)
OUT3G_N: C11G.1 R28G.2 U34G.39 | length 826.7
  Top Layer w5: R28G.2@-2754.04,-1125 C11G.1@-2700.59,-1125 v1(-2682.5,-1125) ; v1(-2010.43,-1118.9) U34G.39@-1979.62,-1118.9
  Int5 (ST) w6: v1(-2682.5,-1125) -2682.07,-1124.57 ccw(c-2699.14,-1107.5) -2675,-1107.5 -2675,-1087.5 cw(c-2662.5,-1087.5) -2662.5,-1075 -2110.52,-1075 cw(c-2110.52,-1133.29) -2069.3,-1092.07 -2061.19,-1100.19 ccw(c-2037.5,-1076.5) -2037.5,-1110 -2031.91,-1110 cw(c-2031.91,-1140.38) v1@-2010.56,-1118.77 ; v1@-2010.56,-1118.77 cw(c-2031.91,-1140.38) v1(-2010.43,-1118.9) v1@-2010.56,-1118.77
OUT3G_P: C11G.2 R44G.2 U34G.38 | length 827
  Top Layer w5: v1(-2667.5,-1125) C11G.2@-2649.41,-1125 R44G.2@-2595.96,-1125 ; v1(-2010.43,-1099.21) U34G.38@-1979.62,-1099.21
  Int6 (SB) w6: v1(-2667.5,-1125) -2667.93,-1124.57 cw(c-2650.86,-1107.5) -2675,-1107.5 -2675,-1087.5 cw(c-2662.5,-1087.5) -2662.5,-1075 -2110.52,-1075 cw(c-2110.52,-1133.29) -2069.3,-1092.07 -2061.19,-1100.19 ccw(c-2037.5,-1076.5) -2037.5,-1110 -2036.47,-1110 ccw(c-2036.47,-1073.17) v1(-2010.43,-1099.21)
OUT3H_N: C11H.1 R28H.2 U34H.39 | length 826.7
  Top Layer w5: R28H.2@-2754.04,-1575 C11H.1@-2700.59,-1575 v1(-2682.5,-1575) ; v1(-2010.43,-1568.9) U34H.39@-1979.62,-1568.9
  Int5 (ST) w6: v1(-2682.5,-1575) -2682.07,-1574.57 ccw(c-2699.14,-1557.5) -2675,-1557.5 -2675,-1537.5 cw(c-2662.5,-1537.5) -2662.5,-1525 -2110.52,-1525 cw(c-2110.52,-1583.29) -2069.3,-1542.07 -2061.19,-1550.19 ccw(c-2037.5,-1526.5) -2037.5,-1560 -2031.91,-1560 cw(c-2031.91,-1590.38) v1@-2010.56,-1568.77 ; v1@-2010.56,-1568.77 cw(c-2031.91,-1590.38) v1(-2010.43,-1568.9) v1@-2010.56,-1568.77
OUT3H_P: C11H.2 R44H.2 U34H.38 | length 827
  Top Layer w5: v1(-2667.5,-1575) C11H.2@-2649.41,-1575 R44H.2@-2595.96,-1575 ; v1(-2010.43,-1549.21) U34H.38@-1979.62,-1549.21
  Int6 (SB) w6: v1(-2667.5,-1575) -2667.93,-1574.57 cw(c-2650.86,-1557.5) -2675,-1557.5 -2675,-1537.5 cw(c-2662.5,-1537.5) -2662.5,-1525 -2110.52,-1525 cw(c-2110.52,-1583.29) -2069.3,-1542.07 -2061.19,-1550.19 ccw(c-2037.5,-1526.5) -2037.5,-1560 -2036.47,-1560 ccw(c-2036.47,-1523.17) v1(-2010.43,-1549.21)
OUT4A_N: C27A.1 R92A.2 U34A.42 | length 426.6
  Top Layer w5: R92A.2@-2366.54,1575 C27A.1@-2313.09,1575 v1(-2295,1575) ; v1(-2010.43,1522.05) U34A.42@-1979.62,1522.05
  Int5 (ST) w6: v1(-2295,1575) -2294.57,1575.43 ccw(c-2311.64,1592.5) -2287.5,1592.5 cw(c-2280,1592.5) -2280,1600 -2179.81,1600 cw(c-2179.81,1500) -2114.15,1575.43 -2093.12,1554.4 ccw(c-2037.5,1610.02) -2037.5,1531.36 -2032.92,1531.36 cw(c-2032.92,1499.56) v1(-2010.43,1522.05)
OUT4A_P: C27A.2 R108A.2 U34A.41 | length 426.9
  Top Layer w5: v1(-2280,1575) C27A.2@-2261.91,1575 R108A.2@-2208.46,1575 ; v1(-2010.43,1541.73) U34A.41@-1979.62,1541.73
  Int6 (SB) w6: v1(-2280,1575) -2280.43,1575.43 cw(c-2263.36,1592.5) -2287.5,1592.5 cw(c-2280,1592.5) -2280,1600 -2179.81,1600 cw(c-2179.81,1500) -2114.15,1575.43 -2093.12,1554.4 ccw(c-2037.5,1610.02) -2037.5,1531.36 -2035.47,1531.36 ccw(c-2035.47,1566.77) v1(-2010.43,1541.73)
OUT4B_N: C27B.1 R92B.2 U34B.42 | length 426.6
  Top Layer w5: R92B.2@-2366.54,1125 C27B.1@-2313.09,1125 v1(-2295,1125) ; v1(-2010.43,1072.05) U34B.42@-1979.62,1072.05
  Int5 (ST) w6: v1(-2295,1125) -2294.57,1125.43 ccw(c-2311.64,1142.5) -2287.5,1142.5 cw(c-2280,1142.5) -2280,1150 -2179.81,1150 cw(c-2179.81,1050) -2114.15,1125.43 -2093.12,1104.4 ccw(c-2037.5,1160.02) -2037.5,1081.36 -2032.92,1081.36 cw(c-2032.92,1049.56) v1(-2010.43,1072.05)
OUT4B_P: C27B.2 R108B.2 U34B.41 | length 426.9
  Top Layer w5: v1(-2280,1125) C27B.2@-2261.91,1125 R108B.2@-2208.46,1125 ; v1(-2010.43,1091.73) U34B.41@-1979.62,1091.73
  Int6 (SB) w6: v1(-2280,1125) -2280.43,1125.43 cw(c-2263.36,1142.5) -2287.5,1142.5 cw(c-2280,1142.5) -2280,1150 -2179.81,1150 cw(c-2179.81,1050) -2114.15,1125.43 -2093.12,1104.4 ccw(c-2037.5,1160.02) -2037.5,1081.36 -2035.47,1081.36 ccw(c-2035.47,1116.77) v1(-2010.43,1091.73)
OUT4C_N: C27C.1 R92C.2 U34C.42 | length 426.6
  Top Layer w5: R92C.2@-2366.54,675 C27C.1@-2313.09,675 v1(-2295,675) ; v1(-2010.43,622.05) U34C.42@-1979.62,622.05
  Int5 (ST) w6: v1(-2295,675) -2294.57,675.43 ccw(c-2311.64,692.5) -2287.5,692.5 cw(c-2280,692.5) -2280,700 -2179.81,700 cw(c-2179.81,600) -2114.15,675.43 -2093.12,654.4 ccw(c-2037.5,710.02) -2037.5,631.36 -2032.92,631.36 cw(c-2032.92,599.56) v1(-2010.43,622.05)
OUT4C_P: C27C.2 R108C.2 U34C.41 | length 426.9
  Top Layer w5: v1(-2280,675) C27C.2@-2261.91,675 R108C.2@-2208.46,675 ; v1(-2010.43,641.73) U34C.41@-1979.62,641.73
  Int6 (SB) w6: v1(-2280,675) -2280.43,675.43 cw(c-2263.36,692.5) -2287.5,692.5 cw(c-2280,692.5) -2280,700 -2179.81,700 cw(c-2179.81,600) -2114.15,675.43 -2093.12,654.4 ccw(c-2037.5,710.02) -2037.5,631.36 -2035.47,631.36 ccw(c-2035.47,666.77) v1(-2010.43,641.73)
OUT4D_N: C27D.1 R92D.2 U34D.42 | length 426.6
  Top Layer w5: R92D.2@-2366.54,225 C27D.1@-2313.09,225 v1(-2295,225) ; v1(-2010.43,172.05) U34D.42@-1979.62,172.05
  Int5 (ST) w6: v1(-2295,225) -2294.57,225.43 ccw(c-2311.64,242.5) -2287.5,242.5 cw(c-2280,242.5) -2280,250 -2179.81,250 cw(c-2179.81,150) -2114.15,225.43 -2093.12,204.4 ccw(c-2037.5,260.02) -2037.5,181.36 -2032.92,181.36 cw(c-2032.92,149.56) v1(-2010.43,172.05)
OUT4D_P: C27D.2 R108D.2 U34D.41 | length 426.9
  Top Layer w5: v1(-2280,225) C27D.2@-2261.91,225 R108D.2@-2208.46,225 ; v1(-2010.43,191.73) U34D.41@-1979.62,191.73
  Int6 (SB) w6: v1(-2280,225) -2280.43,225.43 cw(c-2263.36,242.5) -2287.5,242.5 cw(c-2280,242.5) -2280,250 -2179.81,250 cw(c-2179.81,150) -2114.15,225.43 -2093.12,204.4 ccw(c-2037.5,260.02) -2037.5,181.36 -2035.47,181.36 ccw(c-2035.47,216.77) v1(-2010.43,191.73)
OUT4E_N: C27E.1 R92E.2 U34E.42 | length 426.6
  Top Layer w5: R92E.2@-2366.54,-225 C27E.1@-2313.09,-225 v1(-2295,-225) ; v1(-2010.43,-277.95) U34E.42@-1979.62,-277.95
  Int5 (ST) w6: v1(-2295,-225) -2294.57,-224.57 ccw(c-2311.64,-207.5) -2287.5,-207.5 cw(c-2280,-207.5) -2280,-200 -2179.81,-200 cw(c-2179.81,-300) -2114.15,-224.57 -2093.12,-245.6 ccw(c-2037.5,-189.98) -2037.5,-268.64 -2032.92,-268.64 cw(c-2032.92,-300.44) v1(-2010.43,-277.95)
OUT4E_P: C27E.2 R108E.2 U34E.41 | length 426.9
  Top Layer w5: v1(-2280,-225) C27E.2@-2261.91,-225 R108E.2@-2208.46,-225 ; v1(-2010.43,-258.27) U34E.41@-1979.62,-258.27
  Int6 (SB) w6: v1(-2280,-225) -2280.43,-224.57 cw(c-2263.36,-207.5) -2287.5,-207.5 cw(c-2280,-207.5) -2280,-200 -2179.81,-200 cw(c-2179.81,-300) -2114.15,-224.57 -2093.12,-245.6 ccw(c-2037.5,-189.98) -2037.5,-268.64 -2035.47,-268.64 ccw(c-2035.47,-233.23) v1(-2010.43,-258.27)
OUT4F_N: C27F.1 R92F.2 U34F.42 | length 426.6
  Top Layer w5: R92F.2@-2366.54,-675 C27F.1@-2313.09,-675 v1(-2295,-675) ; v1(-2010.43,-727.95) U34F.42@-1979.62,-727.95
  Int5 (ST) w6: v1(-2295,-675) -2294.57,-674.57 ccw(c-2311.64,-657.5) -2287.5,-657.5 cw(c-2280,-657.5) -2280,-650 -2179.81,-650 cw(c-2179.81,-750) -2114.15,-674.57 -2093.12,-695.6 ccw(c-2037.5,-639.98) -2037.5,-718.64 -2032.92,-718.64 cw(c-2032.92,-750.44) v1(-2010.43,-727.95)
OUT4F_P: C27F.2 R108F.2 U34F.41 | length 426.9
  Top Layer w5: v1(-2280,-675) C27F.2@-2261.91,-675 R108F.2@-2208.46,-675 ; v1(-2010.43,-708.27) U34F.41@-1979.62,-708.27
  Int6 (SB) w6: v1(-2280,-675) -2280.43,-674.57 cw(c-2263.36,-657.5) -2287.5,-657.5 cw(c-2280,-657.5) -2280,-650 -2179.81,-650 cw(c-2179.81,-750) -2114.15,-674.57 -2093.12,-695.6 ccw(c-2037.5,-639.98) -2037.5,-718.64 -2035.47,-718.64 ccw(c-2035.47,-683.23) v1(-2010.43,-708.27)
OUT4G_N: C27G.1 R92G.2 U34G.42 | length 426.6
  Top Layer w5: R92G.2@-2366.54,-1125 C27G.1@-2313.09,-1125 v1(-2295,-1125) ; v1(-2010.43,-1177.95) U34G.42@-1979.62,-1177.95
  Int5 (ST) w6: v1(-2295,-1125) -2294.57,-1124.57 ccw(c-2311.64,-1107.5) -2287.5,-1107.5 cw(c-2280,-1107.5) -2280,-1100 -2179.81,-1100 cw(c-2179.81,-1200) -2114.15,-1124.57 -2093.12,-1145.6 ccw(c-2037.5,-1089.98) -2037.5,-1168.64 -2032.92,-1168.64 cw(c-2032.92,-1200.44) v1(-2010.43,-1177.95)
OUT4G_P: C27G.2 R108G.2 U34G.41 | length 426.9
  Top Layer w5: v1(-2280,-1125) C27G.2@-2261.91,-1125 R108G.2@-2208.46,-1125 ; v1(-2010.43,-1158.27) U34G.41@-1979.62,-1158.27
  Int6 (SB) w6: v1(-2280,-1125) -2280.43,-1124.57 cw(c-2263.36,-1107.5) -2287.5,-1107.5 cw(c-2280,-1107.5) -2280,-1100 -2179.81,-1100 cw(c-2179.81,-1200) -2114.15,-1124.57 -2093.12,-1145.6 ccw(c-2037.5,-1089.98) -2037.5,-1168.64 -2035.47,-1168.64 ccw(c-2035.47,-1133.23) v1(-2010.43,-1158.27)
OUT4H_N: C27H.1 R92H.2 U34H.42 | length 426.6
  Top Layer w5: R92H.2@-2366.54,-1575 C27H.1@-2313.09,-1575 v1(-2295,-1575) ; v1(-2010.43,-1627.95) U34H.42@-1979.62,-1627.95
  Int5 (ST) w6: v1(-2295,-1575) -2294.57,-1574.57 ccw(c-2311.64,-1557.5) -2287.5,-1557.5 cw(c-2280,-1557.5) -2280,-1550 -2179.81,-1550 cw(c-2179.81,-1650) -2114.15,-1574.57 -2093.12,-1595.6 ccw(c-2037.5,-1539.98) -2037.5,-1618.64 -2032.92,-1618.64 cw(c-2032.92,-1650.44) v1(-2010.43,-1627.95)
OUT4H_P: C27H.2 R108H.2 U34H.41 | length 426.9
  Top Layer w5: v1(-2280,-1575) C27H.2@-2261.91,-1575 R108H.2@-2208.46,-1575 ; v1(-2010.43,-1608.27) U34H.41@-1979.62,-1608.27
  Int6 (SB) w6: v1(-2280,-1575) -2280.43,-1574.57 cw(c-2263.36,-1557.5) -2287.5,-1557.5 cw(c-2280,-1557.5) -2280,-1550 -2179.81,-1550 cw(c-2179.81,-1650) -2114.15,-1574.57 -2093.12,-1595.6 ccw(c-2037.5,-1539.98) -2037.5,-1618.64 -2035.47,-1618.64 ccw(c-2035.47,-1583.23) v1(-2010.43,-1608.27)
P1_5V0: C152.1 C156.2 C157.2 FR1.1 U59.8 U65.8 U66.2 | length 1058.2
  Top Layer w20: U59.8@187.5,-1656.99 187.5,-1588.93 cw(c287.5,-1588.93) 287.5,-1488.93 437.5,-1488.93 U65.8@437.5,-1468.01 v2(437.5,-1422.5) ; FR1.1@356.25,-1169.88 cw(c356.25,-1215.9) 388.79,-1183.36 458.21,-1252.78 cw(c387.5,-1323.49) 487.5,-1323.49 U66.2@487.5,-1327.36 v2(487.5,-1377.5)
  Bottom Layer w20: C156.2@479.13,-1562.5 466.79,-1550.16 cw(c537.5,-1479.44) 437.5,-1479.44 v2(437.5,-1422.5) cw(c482.5,-1422.5) 482.5,-1377.5 v2(487.5,-1377.5) ccw(c487.5,-1352.4) 512.6,-1352.4 C157.2@512.6,-1270.69
P2_5V0: C47.2 C148.2 C193.1 FR8.1 U62.8 U63.2 U98.8 | length 1439.6
  Top Layer w20: v4(202.51,1550) U63.2@260.14,1550 ; U62.8@456.99,1162.5 C47.2@541.54,1162.5 v3(541.54,1191.5)
  Int6 (SB) w20: 125.01,1550 v4(202.51,1550) 264.17,1550 cw(c264.17,1450) 364.17,1450 364.17,1300 ; v4(400,1025) 393.46,1031.54 cw(c464.17,1102.25) 364.17,1102.25 364.17,1300 ; v3(541.54,1191.5) 514.09,1191.5 cw(c514.09,1291.5) 443.38,1220.79 364.17,1300
  Bottom Layer w10: U98.8@456.99,1012.5 cw(c456.99,964.5) 490.93,998.44 511.81,977.56 ccw(c548.17,1013.91) 548.17,962.5 C148.2@549.41,962.5
  Bottom Layer w15: v4(400,1025) ccw(c430.18,1055.18) 430.18,1012.5 U98.8@456.99,1012.5
  Bottom Layer w20: 125.01,1550 v4(202.51,1550) ; C148.2@549.41,962.5 549.41,930.7 ccw(c575,930.7) FR8.1@575,905.12
PCIE.PCIE_CLK_N: C284.2 U50.E6 | length 2013.4
  Top Layer w5: U50.E6@216.54,-255.91 v3(236.22,-236.22)
  Bottom Layer w4.7: C284.2@-900,-1324.41 -900,-1319.04 ccw(c-914.45,-1319.04) -914.45,-1304.59 -914.75,-1304.29 -914.75,-984.39 cw(c-426.54,-984.39) -426.54,-496.19 98,-496.19 ccw(c98,-413.39) 180.8,-413.39 180.8,-275.59 181.1,-275.59 cw(c196.85,-275.59) 196.85,-259.84 205.09,-259.84 ccw(c205.09,-244.09) 220.84,-244.09 cw(c228.71,-244.09) 228.71,-236.22 v3(236.22,-236.22)
PCIE.PCIE_CLK_P: C286.2 U50.F6 | length 2013.4
  Top Layer w5: v3(196.85,-236.22) U50.F6@216.54,-216.54
  Bottom Layer w4.7: C286.2@-937.5,-1324.41 -937.5,-1319.04 cw(c-923.05,-1319.04) -923.05,-1304.59 -922.75,-1304.29 -922.75,-984.39 cw(c-426.54,-984.39) -426.54,-488.19 98,-488.19 ccw(c98,-413.39) 172.8,-413.39 172.8,-275.59 172.5,-275.59 cw(c196.85,-275.59) 196.85,-251.24 205.09,-251.24 ccw(c205.09,-244.09) 212.24,-244.09 ccw(c204.36,-244.09) 204.36,-236.22 v3(196.85,-236.22)
PCIE.PCIE_PERST: U50.E14 U99.3 | length 1750.3
  Top Layer w5: v6(-118.11,-236.22) U50.E14@-98.43,-255.91
  Bottom Layer w5: U99.3@-1025.1,-1296.85 -1025.1,-1025.86 cw(c-412.03,-1025.87) -439,-413.39 -118.21,-413.39 ccw(c-118.21,-393.7) -98.53,-393.7 ; v6(-118.11,-236.22) -112.34,-241.99 cw(c-145.95,-275.59) -98.43,-275.59 -98.43,-393.6 -98.53,-393.7 ; -98.43,-393.7 -98.53,-393.7
PCIE.PCIE_PWRGD: U50.R1 U83.5 U84.5 | length 2453.1
  Top Layer w5: U50.R1@413.39,137.8 v3(452.76,137.8)
  Top Layer w10: U83.5@2245.56,-774.11 v4(2284.43,-774.11) ; U84.5@2245.56,-574.11 v4(2284.43,-574.11)
  Int5 (ST) w5: v3(452.76,137.8) 612.63,137.8 cw(c612.63,18.11) 697.26,102.74 1301.52,-501.52 ccw(c1403.48,-399.56) 1403.48,-543.75 2225.89,-543.75 cw(c2225.89,-574.11) 2256.25,-574.11 ; v4(2284.43,-774.11) cw(c2284.43,-745.94) 2256.25,-745.94 2256.25,-574.11 ; v4(2284.43,-574.11) 2256.25,-574.11
PCIE.PCIE_RX0_N: P2.B15 U50.B8 | length 3121.5
  Top Layer w4.7: P2.B15@-1173.15,-2385 -1173.15,-2322 ccw(c-1226.7,-2322) -1188.83,-2284.14 -1188.83,-2214.51 cw(c-1088.83,-2214.51) -1159.55,-2143.8 -901.59,-1885.84 ccw(c-977.95,-1809.47) -869.95,-1809.47 -869.95,-1028.11 cw(c-318.34,-1028.11) -318.34,-476.5 -39.5,-476.5 ccw(c-39.5,-433.07) 3.94,-433.07 3.94,-295.28 cw(c19.68,-295.28) 19.68,-279.53 137.8,-279.53 cw(c137.8,-295.28) 153.54,-295.28 153.54,-381.83 cw(c145.67,-381.83) 145.67,-389.7 cw(c145.67,-384.33) 140.3,-384.33 140.3,-380.05 ccw(c131.76,-380.05) U50.B8@137.8,-374.02
PCIE.PCIE_RX0_P: P2.B14 U50.A8 | length 3159.2
  Top Layer w4.7: P2.B14@-1212.52,-2385 -1212.52,-2322 cw(c-1158.97,-2322) -1196.83,-2284.14 -1196.83,-2214.51 cw(c-1088.83,-2214.51) -1165.2,-2138.14 -907.24,-1880.18 ccw(c-977.95,-1809.47) -877.95,-1809.47 -877.95,-1028.11 cw(c-318.34,-1028.11) -318.34,-468.5 -39.5,-468.5 ccw(c-39.5,-433.07) -4.06,-433.07 -4.06,-295.28 cw(c19.68,-295.28) 19.68,-271.53 137.8,-271.53 cw(c137.8,-295.28) 161.54,-295.28 161.54,-381.83 cw(c145.67,-381.83) 145.67,-397.7 ccw(c145.67,-403.07) 140.3,-403.07 140.3,-407.35 cw(c131.76,-407.35) U50.A8@137.8,-413.39
PCIE.PCIE_RX1_N: P2.B20 U50.D11 | length 2743.3
  Top Layer w4.7: P2.B20@-976.3,-2385 -976.3,-2322 ccw(c-1030.34,-2322) -992.13,-2283.8 -992.13,-2218.59 cw(c-892.13,-2218.59) -962.84,-2147.88 -811.03,-1996.07 ccw(c-887.4,-1919.71) -779.4,-1919.71 -779.4,-1051.61 cw(c-243.79,-1051.61) -243.79,-516 -39.5,-516 ccw(c-39.5,-433.07) 43.43,-433.07 43.43,-326.83 ccw(c27.56,-326.83) 27.56,-310.96 cw(c27.56,-305.59) 22.19,-305.59 22.19,-301.31 ccw(c13.65,-301.31) U50.D11@19.69,-295.28
PCIE.PCIE_RX1_P: P2.B19 U50.C11 | length 2730.6
  Top Layer w4.7: P2.B19@-1015.67,-2385 -1015.67,-2322 cw(c-962.6,-2322.01) -1000.13,-2284.48 -1000.13,-2218.59 cw(c-892.13,-2218.59) -968.49,-2142.22 -816.69,-1990.42 ccw(c-887.4,-1919.71) -787.4,-1919.71 -787.4,-1051.61 cw(c-243.79,-1051.61) -243.79,-508 -39.5,-508 ccw(c-39.5,-433.07) 35.43,-433.07 35.43,-326.83 ccw(c27.56,-326.83) 27.56,-318.96 ccw(c27.56,-324.33) 22.19,-324.33 22.19,-328.61 cw(c13.65,-328.61) U50.C11@19.69,-334.65
PCIE.PCIE_RX2_N: P2.B24 U50.B10 | length 2577.8
  Top Layer w4.7: P2.B24@-818.82,-2385 -818.82,-2322 ccw(c-872.37,-2322) -834.5,-2284.14 -834.5,-2234.19 cw(c-734.5,-2234.19) -805.21,-2163.48 -724.42,-2082.69 ccw(c-800.79,-2006.32) -692.79,-2006.32 -692.79,-1074.98 cw(c-173.18,-1074.98) -173.18,-555.37 -39.5,-555.37 ccw(c-39.5,-433.07) 82.8,-433.07 82.8,-405.57 ccw(c66.93,-405.57) 66.93,-389.7 cw(c66.93,-384.33) 61.56,-384.33 61.56,-380.05 ccw(c53.02,-380.05) U50.B10@59.06,-374.02
PCIE.PCIE_RX2_P: P2.B23 U50.A10 | length 2565.2
  Top Layer w4.7: P2.B23@-858.19,-2385 -858.19,-2322 cw(c-804.64,-2322) -842.5,-2284.14 -842.5,-2234.19 cw(c-734.5,-2234.19) -810.87,-2157.83 -730.08,-2077.03 ccw(c-800.79,-2006.32) -700.79,-2006.32 -700.79,-1074.98 cw(c-173.18,-1074.98) -173.18,-547.37 -39.5,-547.37 ccw(c-39.5,-433.07) 74.8,-433.07 74.8,-405.57 ccw(c66.93,-405.57) 66.93,-397.7 ccw(c66.93,-403.07) 61.56,-403.07 61.56,-407.35 cw(c53.02,-407.35) U50.A10@59.06,-413.39
PCIE.PCIE_RX3_N: P2.B28 U50.D9 | length 2572.7
  Top Layer w4.7: P2.B28@-661.34,-2385 -661.34,-2322 ccw(c-714.89,-2322) -677.02,-2284.14 -677.02,-2242.07 cw(c-577.02,-2242.07) -647.73,-2171.36 -633.86,-2157.48 ccw(c-700.7,-2090.64) -606.17,-2090.64 -606.17,-1098.22 cw(c-102.56,-1098.22) -102.56,-594.61 -33.95,-594.61 ccw(c-33.95,-438.61) 122.05,-438.61 122.05,-326.71 ccw(c106.3,-326.71) 106.3,-310.96 cw(c106.3,-305.59) 100.93,-305.59 100.93,-301.31 ccw(c92.39,-301.31) U50.D9@98.43,-295.28
PCIE.PCIE_RX3_P: P2.B27 U50.C9 | length 2560.2
  Top Layer w4.7: P2.B27@-700.71,-2385 -700.71,-2322 cw(c-647.16,-2322) -685.02,-2284.14 -685.02,-2242.07 cw(c-577.02,-2242.07) -653.39,-2165.7 -639.52,-2151.82 ccw(c-700.7,-2090.64) -614.17,-2090.64 -614.17,-1098.22 cw(c-102.56,-1098.22) -102.56,-586.61 -33.95,-586.61 ccw(c-33.95,-438.61) 114.05,-438.61 114.05,-326.71 ccw(c106.3,-326.71) 106.3,-318.96 ccw(c106.3,-324.33) 100.93,-324.33 100.93,-328.61 cw(c92.39,-328.61) U50.C9@98.43,-334.65
PCIE.PCIE_TX0_N: C281.2 U50.B4 | length 1903.1
  Top Layer w5: U50.B4@295.28,-374.02 v3(314.96,-393.7)
  Bottom Layer w4.7: C281.2@-812.5,-1324.41 -812.5,-1318.94 ccw(c-827.25,-1318.94) -827.25,-1304.19 -827.25,-1019.75 cw(c-342.94,-1019.75) -342.94,-535.43 -157.48,-535.43 246.45,-535.43 256.03,-535.43 ccw(c256.03,-452.76) 338.71,-452.76 338.71,-425.26 ccw(c322.83,-425.26) 322.83,-409.39 cw(c322.83,-401.51) 314.96,-401.51 v3(314.96,-393.7)
PCIE.PCIE_TX0_P: C283.2 U50.A4 | length 1890.6
  Top Layer w5: U50.A4@295.28,-413.39 v3(314.96,-433.07)
  Bottom Layer w4.7: C283.2@-850,-1324.41 -850,-1318.94 cw(c-835.25,-1318.94) -835.25,-1304.19 -835.25,-1019.75 cw(c-342.94,-1019.75) -342.94,-527.43 -157.48,-527.43 246.45,-527.43 256.03,-527.43 ccw(c256.03,-452.76) 330.71,-452.76 330.71,-425.26 ccw(c322.83,-425.26) 322.83,-417.39 ccw(c322.83,-425.26) 314.96,-425.26 v3(314.96,-433.07)
PCIE.PCIE_TX1_N: C279.2 U50.D5 | length 1993.1
  Top Layer w5: U50.D5@255.91,-295.28 v3(275.59,-314.96)
  Bottom Layer w4.7: C279.2@-725,-1324.41 -725,-1318.94 ccw(c-739.75,-1318.94) -739.75,-1304.19 -739.75,-1025.94 cw(c-288.74,-1025.94) -288.74,-574.93 256.1,-574.93 ccw(c256.1,-452.95) 378.08,-452.95 378.08,-393.7 ccw(c354.33,-393.7) 354.33,-369.95 314.83,-369.95 cw(c314.83,-354.46) 299.34,-354.46 299.34,-346.52 ccw(c283.46,-346.52) 283.46,-330.65 cw(c283.46,-322.77) 275.59,-322.77 v3(275.59,-314.96)
PCIE.PCIE_TX1_P: C280.2 U50.C5 | length 1980.5
  Top Layer w5: U50.C5@255.91,-334.65 v3(275.59,-354.33)
  Bottom Layer w4.7: C280.2@-762.5,-1324.41 -762.5,-1318.94 cw(c-747.75,-1318.94) -747.75,-1304.19 -747.75,-1025.94 cw(c-288.74,-1025.94) -288.74,-566.93 256.1,-566.93 ccw(c256.1,-452.95) 370.08,-452.95 370.08,-393.7 ccw(c354.33,-393.7) 354.33,-377.95 314.83,-377.95 cw(c314.83,-354.46) 291.34,-354.46 291.34,-346.52 ccw(c283.46,-346.52) 283.46,-338.65 ccw(c283.46,-346.52) 275.59,-346.52 v3(275.59,-354.33)
PCIE.PCIE_TX2_N: C277.2 U50.B6 | length 2153.8
  Top Layer w5: U50.B6@216.54,-374.02 v3(236.22,-393.7)
  Bottom Layer w4.7: C277.2@-637.5,-1324.41 -637.5,-1318.94 ccw(c-652.25,-1318.94) -652.25,-1304.19 -652.25,-1071.93 cw(c-194.62,-1071.93) -194.62,-614.3 277.45,-614.3 ccw(c277.45,-474.3) 417.45,-474.3 417.45,-354.33 ccw(c393.83,-354.33) 393.83,-330.71 354.33,-330.71 cw(c354.33,-315.09) 338.71,-315.09 338.71,-314.96 ccw(c314.96,-314.96) 314.96,-291.21 275.59,-291.21 ccw(c275.59,-314.83) 251.97,-314.83 251.97,-401.51 cw(c244.09,-401.51) 244.09,-409.39 cw(c244.09,-401.51) 236.22,-401.51 v3(236.22,-393.7)
PCIE.PCIE_TX2_P: C278.2 U50.A6 | length 2141.2
  Top Layer w5: U50.A6@216.54,-413.39 v3(236.22,-433.07)
  Bottom Layer w4.7: C278.2@-675,-1324.41 -675,-1318.94 cw(c-660.25,-1318.94) -660.25,-1304.19 -660.25,-1071.93 cw(c-194.62,-1071.93) -194.62,-606.3 277.45,-606.3 ccw(c277.45,-474.3) 409.45,-474.3 409.45,-354.33 ccw(c393.83,-354.33) 393.83,-338.71 354.33,-338.71 cw(c354.33,-315.09) 330.71,-315.09 330.71,-314.96 ccw(c314.96,-314.96) 314.96,-299.21 275.59,-299.21 ccw(c275.59,-314.83) 259.97,-314.83 259.97,-401.51 cw(c244.09,-401.51) 244.09,-417.39 ccw(c244.09,-425.26) 236.22,-425.26 v3(236.22,-433.07)
PCIE.PCIE_TX3_N: C273.2 U50.D7 | length 2156.7
  Top Layer w5: U50.D7@177.17,-295.28 v3(196.85,-314.96)
  Bottom Layer w4.7: C273.2@-550,-1324.41 -550,-1318.94 ccw(c-564.75,-1318.94) -564.75,-1304.19 -564.75,-1100.69 cw(c-117.73,-1100.69) -117.73,-653.67 300.82,-653.67 ccw(c300.82,-497.67) 456.82,-497.67 456.82,-334.65 ccw(c413.51,-334.65) 413.51,-291.34 393.7,-291.34 cw(c393.7,-275.72) 378.08,-275.72 378.08,-275.59 ccw(c354.33,-275.59) 354.33,-251.84 275.59,-251.84 ccw(c275.59,-314.83) 212.6,-314.83 212.6,-322.77 cw(c204.72,-322.77) 204.72,-330.65 cw(c204.72,-322.77) 196.85,-322.77 v3(196.85,-314.96)
PCIE.PCIE_TX3_P: C276.2 U50.C7 | length 2144.2
  Top Layer w5: U50.C7@177.17,-334.65 v3(196.85,-354.33)
  Bottom Layer w4.7: C276.2@-587.5,-1324.41 -587.5,-1318.94 cw(c-572.75,-1318.94) -572.75,-1304.19 -572.75,-1100.69 cw(c-117.73,-1100.69) -117.73,-645.67 300.82,-645.67 ccw(c300.82,-497.67) 448.82,-497.67 448.82,-334.65 ccw(c413.51,-334.65) 413.51,-299.34 393.7,-299.34 cw(c393.7,-275.72) 370.08,-275.72 370.08,-275.59 ccw(c354.33,-275.59) 354.33,-259.84 275.59,-259.84 ccw(c275.59,-314.83) 220.6,-314.83 220.6,-322.77 cw(c204.72,-322.77) 204.72,-338.65 ccw(c204.72,-346.52) 196.85,-346.52 v3(196.85,-354.33)
PER0_N: C281.1 P2.A17 | length 1136.6
  Bottom Layer w4.7: P2.A17@-1094.41,-2385 -1094.41,-2315.51 ccw(c-1109.99,-2315.51) -1109.99,-2299.92 -1109.99,-2204.22 cw(c-1049.33,-2204.22) -1092.23,-2161.32 -858.84,-1927.94 ccw(c-935.35,-1851.43) -827.15,-1851.43 -827.15,-1395.71 ccw(c-827.15,-1381.06) -812.5,-1381.06 C281.1@-812.5,-1375.59
PER0_P: C283.1 P2.A16 | length 1136.6
  Bottom Layer w4.7: P2.A16@-1133.78,-2385 -1133.78,-2315.51 cw(c-1118.19,-2315.51) -1118.19,-2299.92 -1118.19,-2204.22 cw(c-1049.33,-2204.22) -1098.03,-2155.53 -864.64,-1922.14 ccw(c-935.35,-1851.43) -835.35,-1851.43 -835.35,-1395.71 cw(c-835.35,-1381.06) -850,-1381.06 C283.1@-850,-1375.59
PER1_N: C279.1 P2.A22 | length 1089.7
  Bottom Layer w4.7: P2.A22@-897.56,-2385 -897.56,-2315.51 ccw(c-913.24,-2315.51) -913.24,-2299.82 -913.24,-2232.17 cw(c-813.24,-2232.17) -883.95,-2161.45 -771.38,-2048.88 ccw(c-847.75,-1972.51) -739.75,-1972.51 -739.75,-1395.81 ccw(c-739.75,-1381.06) -725,-1381.06 C279.1@-725,-1375.59
PER1_P: C280.1 P2.A21 | length 1089.7
  Bottom Layer w4.7: P2.A21@-936.93,-2385 -936.93,-2315.51 cw(c-921.24,-2315.51) -921.24,-2299.82 -921.24,-2232.17 cw(c-813.24,-2232.17) -889.61,-2155.8 -777.04,-2043.23 ccw(c-847.75,-1972.51) -747.75,-1972.51 -747.75,-1395.81 cw(c-747.75,-1381.06) -762.5,-1381.06 C280.1@-762.5,-1375.59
